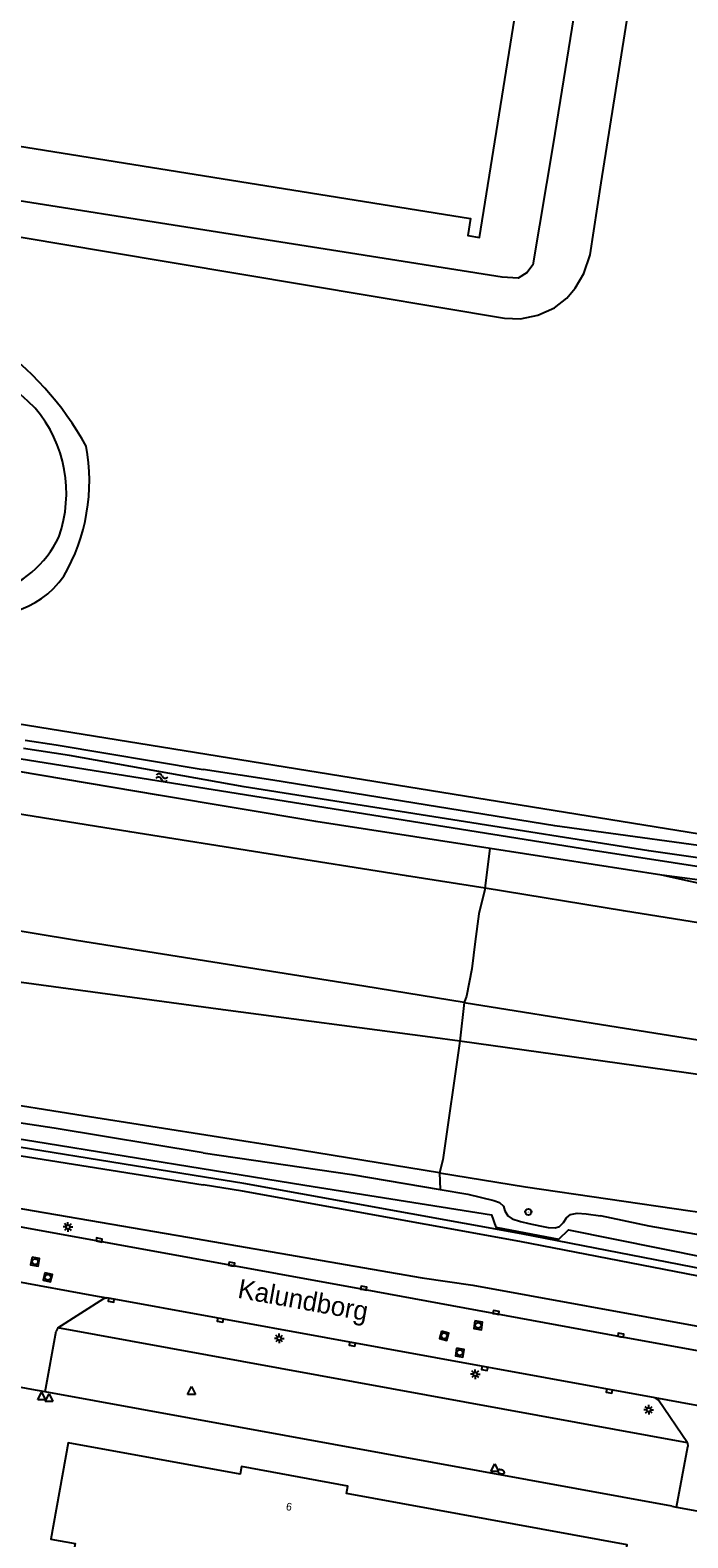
# Model space of a CAD drawing. Extents: x 131000 to 133013, y 393000 to 396501.
# Drawn here: x 131977.5 to 132063, y 394393.9 to 394589.8 of the extents above; entities that cross this region are included whole.
import ezdxf

# ---------------------------------------------------------------- set-up
doc = ezdxf.new("R2010")
doc.units = 0
for name, color, linetype in [('gg-afsc-hekwerk', 7, 'Continuous'), ('gg-anno-huisnummerreeks BGT', 7, 'Continuous'), ('gg-anno-openbare ruimte label', 7, 'Continuous'), ('gg-bbg-hoofdgebouw', 7, 'Continuous'), ('gg-knt-BGT kruinlijn', 7, 'Continuous'), ('gg-knt-verharding', 7, 'Continuous'), ('gg-kntw-bovenkant insteek waterloop', 7, 'Continuous'), ('gg-kntw-waterlijn', 7, 'Continuous'), ('gt-grn-groengrens', 7, 'Continuous'), ('gt-symb-brandkraan', 7, 'Continuous'), ('gt-symb-hoogtemerk', 7, 'Continuous'), ('gt-symb-kolk', 7, 'Continuous'), ('gt-symb-lichtmast', 7, 'Continuous'), ('gt-symb-rioolschacht', 7, 'Continuous'), ('gt-symb-waterafsluiter', 7, 'Continuous'), ('gt-symb-watersymbool', 7, 'Continuous'), ('gx-grn-maaiveld', 7, 'Continuous')]:
    doc.layers.add(name, color=color, linetype=linetype)

# ---------------------------------------------------------------- blocks, each defined once
blk = doc.blocks.new('gt0-WA')
at = {"layer": 'gt-symb-watersymbool'}
for centre, start, end in [((-0.32, 0.02), 28.0725, 151.9275), ((0.43, 0.42), 208.0725, 331.9275), ((-0.32, -0.43), 28.0725, 151.9275), ((0.43, -0.03), 208.0725, 331.9275)]:
    blk.add_arc(centre, 0.425, start, end, dxfattribs=at)
blk = doc.blocks.new('gt0-RS')
at = {"layer": 'gt-symb-rioolschacht'}
blk.add_lwpolyline([(-0.5, -0.5), (0.5, -0.5), (0.5, 0.5), (-0.5, 0.5)], close=True, dxfattribs=at)
blk.add_circle((0, 0), 0.375, dxfattribs=at)
blk = doc.blocks.new('gt0-KOLK')
at = {"layer": 'gt-symb-kolk'}
blk.add_lwpolyline([(0, 0), (0.37, 0), (0.37, 0.4), (-0.38, 0.4), (-0.38, 0), (0, 0)], dxfattribs=at)
blk = doc.blocks.new('gt0-HMERK')
at = {"layer": 'gt-symb-hoogtemerk'}
blk.add_circle((0, 0), 0.4, dxfattribs=at)
blk.add_text('N.A.P', height=0.2, dxfattribs=at).set_placement((-0.35, -0.1))
blk = doc.blocks.new('gt0-LMAST')
at = {"layer": 'gt-symb-lichtmast'}
for p, q in [((-0.18, 0.17), (-0.45, 0.44)), ((-0.01, 0.25), (-0.01, 0.62)), ((0.17, 0.17), (0.44, 0.44)), ((-0.26, 0), (-0.63, 0)), ((-0.18, -0.18), (-0.45, -0.45)), ((-0.01, -0.25), (-0.01, -0.63)), ((0.44, -0.45), (0.17, -0.18)), ((0.24, 0), (0.62, 0))]:
    blk.add_line(p, q, dxfattribs=at)
blk.add_circle((-0.01, 0), 0.25, dxfattribs=at)
blk = doc.blocks.new('gt0-BR')
at = {"layer": 'gt-symb-brandkraan'}
for centre, radius, start, end in [((-0.24, 0), 0.206, 107.5669, 252.4331), ((0.6, -2.66), 3, 106.892, 107.5669), ((0, -0.69), 0.938, 73.108, 106.892), ((-0.6, -2.66), 3, 72.4331, 73.108), ((0.24, 0), 0.206, 287.567, 72.4331), ((0.6, 2.66), 3, 252.4331, 253.108), ((0, 0.69), 0.938, 253.108, 286.8921), ((-0.6, 2.66), 3, 286.8921, 287.567)]:
    blk.add_arc(centre, radius, start, end, dxfattribs=at)
blk = doc.blocks.new('gt0-WAFSL')
at = {"layer": 'gt-symb-waterafsluiter'}
for p, q in [((-0.5, -0.33), (0, 0.67)), ((0, 0.67), (0.5, -0.33)), ((0.5, -0.33), (-0.5, -0.33))]:
    blk.add_line(p, q, dxfattribs=at)

msp = doc.modelspace()

# ---------------------------------------------------------------- linework, layer by layer
at = {"layer": 'gg-afsc-hekwerk'}
for p, q in [((131974.2, 394500), (132068.87, 394484.71)), ((131974.2, 394500), (132068.87, 394484.71)), ((131977.73, 394413.21), (131972.86, 394414.1)), ((131979.45, 394412.9), (131977.73, 394413.21)), ((132060.94, 394398.02), (131979.45, 394412.9)), ((132060.94, 394398.02), (132061.56, 394397.91)), ((132061.56, 394397.91), (132066.58, 394396.99))]:
    msp.add_line(p, q, dxfattribs=at)
at = {"layer": 'gg-bbg-hoofdgebouw'}
for points in [[(131826.92, 394598.72), (132034.78, 394565.38), (132034.42, 394563.15), (132035.94, 394562.91), (132051.66, 394661.02), (131936.69, 394679.61)], [(132046.43, 394349.13), (132048.1, 394358.23), (132048.2, 394358.21), (132051.43, 394375.95), (132051.33, 394375.96), (132052.18, 394380.61), (132052.87, 394380.49), (132054.97, 394392.06), (132055.14, 394393), (132018.64, 394399.67), (132018.82, 394400.65), (132004.99, 394403.18), (132004.81, 394402.19), (131982.46, 394406.27), (131980.18, 394393.76), (131983.38, 394393.18), (131982.74, 394389.69), (131982.64, 394389.71), (131979.19, 394370.63), (131988.51, 394368.94)]]:
    msp.add_lwpolyline(points, dxfattribs=at)
at = {"layer": 'gg-knt-BGT kruinlijn'}
msp.add_lwpolyline([(131882.09, 394453.77), (131908.72, 394449.35), (131938.59, 394443.9), (131966.62, 394438.37), (131997.99, 394432.98), (132028.47, 394427.7), (132035.06, 394426.77), (132065.03, 394421.3), (132101.8, 394414.25), (132138.25, 394406.78)], dxfattribs=at)
at = {"layer": 'gg-knt-verharding'}
for p, q in [((132058.79, 394412.12), (131987.46, 394425.11)), ((131979.45, 394412.9), (131980.89, 394420.78)), ((131981.12, 394421.22), (131980.89, 394420.78)), ((132074.24, 394409.3), (132058.79, 394412.12)), ((132059.22, 394411.8), (132058.79, 394412.12)), ((132063, 394406.25), (132059.22, 394411.8)), ((132063, 394406.25), (132063.02, 394405.8)), ((132061.56, 394397.91), (132063.02, 394405.8))]:
    msp.add_line(p, q, dxfattribs=at)
for points in [[(132141.77, 394404.13), (132121.14, 394407.9), (132054.3, 394420.05), (132020.85, 394426.18), (131965.36, 394436.27), (131919.64, 394444.61), (131904.42, 394447.36), (131889.17, 394450.15), (131884.06, 394451.05)], [(131964.98, 394429.23), (131985.74, 394425.41), (131987.46, 394425.11)], [(131981.12, 394421.22), (131987.07, 394425.01), (131987.46, 394425.11)]]:
    msp.add_lwpolyline(points, dxfattribs=at)
at = {"layer": 'gg-kntw-bovenkant insteek waterloop'}
msp.add_line((131994.19, 394490.41), (131975.99, 394493.49), dxfattribs=at)
for points in [[(131976.87, 394497.57), (131980.88, 394496.96), (132000, 394493.75)], [(131873.98, 394460.11), (131933.34, 394450.39), (132000, 394439.79)], [(132136.37, 394413.97), (132041.21, 394432.44), (132005.14, 394438.97), (132000, 394439.79)]]:
    msp.add_lwpolyline(points, dxfattribs=at)
for centre, radius, start, end in [((131948.82, 394515.78), 41.16, 29.0688, 80.5927), ((131960.65, 394531.23), 24.56, 329.8217, 10.6624), ((131972.44, 394525.45), 11.51, 244.3733, 325.1971)]:
    msp.add_arc(centre, radius, start, end, dxfattribs=at)
at = {"layer": 'gg-kntw-waterlijn'}
for points in [[(131802.44, 394473.43), (131812.84, 394471.77), (131821.8, 394470.17), (131834.66, 394468.1), (131859.12, 394464.34), (131927.71, 394453.47), (131977.97, 394445.49), (132013.25, 394439.77), (132037.49, 394435.91), (132038.07, 394434.28), (132046.28, 394432.75), (132047.54, 394433.95), (132124.98, 394418.36), (132139.72, 394415.63)], [(132000.16, 394440.78), (131965.33, 394446.42), (131926.16, 394452.62), (131891.32, 394458.13), (131845.19, 394465.8), (131823.7, 394469.18), (131805.37, 394472.07)], [(132139.72, 394415.63), (132136.56, 394414.95), (132041.4, 394433.42), (132005.31, 394439.96), (132000.16, 394440.78)]]:
    msp.add_lwpolyline(points, dxfattribs=at)
for centre, radius, start, end in [((131934.12, 394494.07), 64.17, 46.6555, 65.1507), ((131965.2, 394529.71), 17.02, 340.2914, 40.3784), ((131968.56, 394530.1), 14.08, 287.0347, 334.1833)]:
    msp.add_arc(centre, radius, start, end, dxfattribs=at)
at = {"layer": 'gt-grn-groengrens'}
msp.add_line((132063, 394406.25), (131981.12, 394421.22), dxfattribs=at)
at = {"layer": 'gx-grn-maaiveld'}
for p, q in [((132036.67, 394478.36), (132037.32, 394483.5)), ((132059.64, 394480.02), (132037.32, 394483.5)), ((132102.28, 394470.59), (132059.64, 394480.02)), ((132033.96, 394463.49), (132033.38, 394458.46)), ((132000, 394443.95), (132019.32, 394441.15)), ((132019.32, 394441.15), (132030.85, 394439.2)), ((132030.74, 394441.36), (132030.85, 394439.2)), ((132030.85, 394439.2), (132034.43, 394438.58))]:
    msp.add_line(p, q, dxfattribs=at)
for points in [[(132053.96, 394627.45), (132045.54, 394575.05), (132042.86, 394559.35), (132042.13, 394558.35), (132040.98, 394557.63), (132038.88, 394557.72), (132017.51, 394561.13), (131955.42, 394570.9), (131841.5, 394589.17), (131830.06, 394591.05)], [(131804.57, 394608.97), (131804.57, 394597.72), (131804.84, 394595.05), (131805.34, 394593.58), (131806.22, 394592.29), (131807.72, 394591.11), (131809.85, 394590.32), (131819.19, 394588.82), (131888.59, 394577.68), (131987.42, 394561.09), (132039.2, 394552.4), (132041.26, 394552.34), (132043.54, 394552.81), (132045.7, 394553.75), (132047.32, 394555.03), (132048.39, 394556.31), (132049.53, 394558.22), (132050.34, 394560.63), (132051.75, 394570.01), (132059.11, 394616.14), (132059.53, 394618.56)], [(132033.96, 394463.49), (132020.91, 394465.6), (131983.52, 394471.55), (131940.74, 394478.61), (131895.79, 394485.81), (131853.7, 394492.51), (131809.04, 394499.63), (131765.33, 394506.63), (131726.06, 394512.85), (131682.77, 394519.67), (131648.53, 394525.24)], [(132033.38, 394458.46), (132029.51, 394459), (132002.6, 394462.54), (131976.36, 394466.1), (131941.58, 394471.15), (131906.12, 394476.45), (131862.98, 394483.36), (131828.14, 394488.86), (131800.75, 394493.22), (131774.67, 394497.34), (131757.41, 394500.15), (131739.27, 394502.97), (131716.81, 394506.48), (131679.84, 394512.41), (131652.07, 394516.93), (131646.66, 394517.79)], [(132036.67, 394478.36), (132026.47, 394479.95), (131990.46, 394485.67), (131963.13, 394490.05), (131936.76, 394494.3), (131911.87, 394498.3), (131883.79, 394502.78), (131854.46, 394507.45)], [(132393.51, 394448.27), (132393.24, 394448.21), (132391.77, 394448.26), (132388.81, 394448.54), (132378.36, 394449.82), (132370.18, 394450.17), (132341.3, 394453.29), (132297.88, 394457.11), (132263.93, 394460.34), (132238.47, 394462.99), (132214.65, 394465.32), (132175.47, 394469.61), (132158.14, 394471.88), (132141.87, 394473.43), (132072.18, 394481.18), (132057.95, 394483.2), (132005.32, 394491.53), (131982.61, 394495.58), (131976.63, 394496.49)], [(131976.35, 394495.15), (132050.16, 394483.39), (132072.09, 394479.98), (132088.56, 394478), (132177.69, 394468.26), (132211.95, 394464.45), (132269.05, 394458.9), (132323.32, 394453.95), (132340.29, 394452.47), (132365.93, 394449.82), (132377.92, 394448.15), (132384.13, 394447.41), (132389.62, 394446.78), (132393.17, 394446.43)], [(132393.43, 394449.5), (132387.44, 394449.72), (132352.23, 394453.53), (132333.88, 394455.38), (132308.73, 394457.32), (132296.22, 394458.36), (132283.38, 394459.75), (132260.71, 394462.01), (132225.61, 394465.96), (132166.98, 394472.1), (132155.67, 394473.85), (132142.62, 394475.19), (132115.81, 394478.14), (132092.48, 394480.92), (132071.73, 394482.91), (132045.73, 394486.44), (132009.08, 394492.36), (132000, 394493.75)], [(132037.32, 394483.5), (132014.65, 394487.02), (131994.19, 394490.41)], [(132392.83, 394444.86), (132378.29, 394446.66), (132359.72, 394448.75), (132328.43, 394451.58), (132278.73, 394456.76), (132264.12, 394457.79), (132211.33, 394463), (132176.68, 394466.59), (132136, 394470.78), (132095.13, 394475.37), (132081.12, 394477.21), (132059.64, 394480.02)], [(132030.74, 394441.36), (132010.82, 394444.61), (131984.4, 394448.75), (131958.26, 394452.91), (131925.08, 394458.17), (131903.62, 394461.61), (131892.41, 394463.41), (131874.5, 394466.24), (131859.47, 394468.57), (131842.56, 394471.39), (131831.57, 394473.18), (131803.98, 394477.71)], [(132036.67, 394478.36), (132035.84, 394475), (132035.36, 394471.42), (132034.94, 394467.87), (132034.25, 394464.31), (132033.96, 394463.49)], [(132390.03, 394421.82), (132382.86, 394422.92), (132351.64, 394427.96), (132316.55, 394433.59), (132294.78, 394437.07), (132270.12, 394441), (132245.02, 394445), (132219.44, 394449.06), (132194.93, 394452.97), (132173.38, 394456.44), (132143.11, 394461.24), (132122.55, 394464.5), (132101.1, 394468), (132078.77, 394471.56), (132054.67, 394475.4), (132036.67, 394478.36)], [(132000, 394443.95), (131980.65, 394447.15), (131938.32, 394453.51), (131923.18, 394455.67), (131903.3, 394459.06), (131851.25, 394466.97), (131834.06, 394470), (131817.5, 394472.28)], [(132033.96, 394463.49), (132052.91, 394460.47), (132080.96, 394455.98), (132110.84, 394451.17), (132141.78, 394446.25), (132173.79, 394441.09), (132209.08, 394435.46), (132244.82, 394429.77), (132278.27, 394424.48), (132311.44, 394419.19), (132351.85, 394412.84), (132388.48, 394406.97)], [(132033.38, 394458.46), (132031.17, 394443.06), (132030.74, 394441.36)], [(132387.58, 394403.21), (132365.5, 394406.81), (132323.87, 394413.44), (132293.91, 394418.16), (132261.12, 394423.42), (132211.09, 394431.46), (132182.58, 394436.04), (132152.58, 394440.93), (132126.86, 394445), (132098.31, 394449.38), (132060.36, 394454.68), (132033.38, 394458.46)], [(132030.74, 394441.36), (132041.92, 394439.53), (132063.34, 394436.41), (132072.43, 394435.22), (132077.9, 394434.67), (132085.99, 394433.87), (132094.73, 394432.88), (132113.14, 394430.72), (132118.21, 394430.12), (132121.4, 394429.78), (132122.17, 394429.67), (132122.52, 394430.6), (132132.04, 394429.35), (132153.87, 394425.89), (132161.29, 394424.68), (132188.02, 394420.5), (132219.12, 394415.45), (132255.99, 394409.47), (132302.9, 394401.98), (132354.54, 394393.66), (132385.57, 394388.69)], [(132034.43, 394438.58), (132037.83, 394437.76), (132038.56, 394437.52), (132039.06, 394437.01), (132039.26, 394436.41), (132039.63, 394435.75), (132040.18, 394435.36), (132041.29, 394435.01), (132042.34, 394434.76), (132043.8, 394434.45), (132044.89, 394434.27), (132045.77, 394434.21), (132046.36, 394434.39), (132046.87, 394434.9), (132047.25, 394435.52), (132047.8, 394435.95), (132048.66, 394436.1), (132049.83, 394436.02), (132051.7, 394435.77)], [(132140.79, 394417.42), (132139.83, 394417.73), (132128.84, 394420.16), (132121.84, 394421.71), (132113.87, 394423.68), (132097.16, 394427.31), (132086.99, 394429.35), (132058.01, 394434.42), (132051.7, 394435.77)]]:
    msp.add_lwpolyline(points, dxfattribs=at)

# ---------------------------------------------------------------- block references
at = {"layer": 'gt-symb-brandkraan', "rotation": -16.386305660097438}
msp.add_blockref('gt0-BR', (132038.75, 394402.51), dxfattribs=at)
at = {"layer": 'gt-symb-hoogtemerk'}
msp.add_blockref('gt0-HMERK', (132042.3, 394436.27), dxfattribs=at)
at = {"layer": 'gt-symb-kolk'}
for p, rotation in [((131986.45, 394432.43), -10.309970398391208), ((132003.69, 394429.29), -10.30997039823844), ((132020.85, 394426.18), -10.366322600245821), ((131988.07, 394425), 169.54790475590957), ((132002.27, 394422.42), 169.69002960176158), ((132038.07, 394423.02), -10.366322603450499), ((132054.3, 394420.05), -10.30997039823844), ((132019.45, 394419.28), 169.6336773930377), ((132036.66, 394416.14), 169.63367739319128), ((132052.86, 394413.2), 169.69002960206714)]:
    msp.add_blockref('gt0-KOLK', p, dxfattribs=dict(at, rotation=rotation))
at = {"layer": 'gt-symb-lichtmast'}
for p in [(131982.43, 394434.32), (132009.9, 394419.84), (132035.4, 394415.19), (132057.96, 394410.57)]:
    msp.add_blockref('gt0-LMAST', p, dxfattribs=at)
at = {"layer": 'gt-symb-rioolschacht'}
for p, rotation in [((131978.15, 394429.8), -100.30997039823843), ((131979.8, 394427.78), -103.29958432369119), ((132035.77, 394421.54), -98.91603673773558), ((132031.35, 394420.17), -104.30027744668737), ((132033.38, 394417.99), -99.37757912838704)]:
    msp.add_blockref('gt0-RS', p, dxfattribs=dict(at, rotation=rotation))
at = {"layer": 'gt-symb-waterafsluiter'}
for p in [(131978.99, 394412.17), (131979.97, 394411.96), (131998.49, 394412.9), (132037.93, 394402.88)]:
    msp.add_blockref('gt0-WAFSL', p, dxfattribs=at)
at = {"layer": 'gt-symb-watersymbool', "rotation": -9.20796905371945}
msp.add_blockref('gt0-WA', (131994.57, 394492.72), dxfattribs=at)

# ---------------------------------------------------------------- texts
at = {"layer": 'gg-anno-huisnummerreeks BGT'}
msp.add_text('6', height=1, rotation=349.6, dxfattribs=at).set_placement((132010.72, 394397.55))
at = {"layer": 'gg-anno-openbare ruimte label'}
msp.add_text('Kalundborg', height=2.5, rotation=349.7, dxfattribs=at).set_placement((132004.38, 394425.14))

doc.saveas('drawing.dxf')
